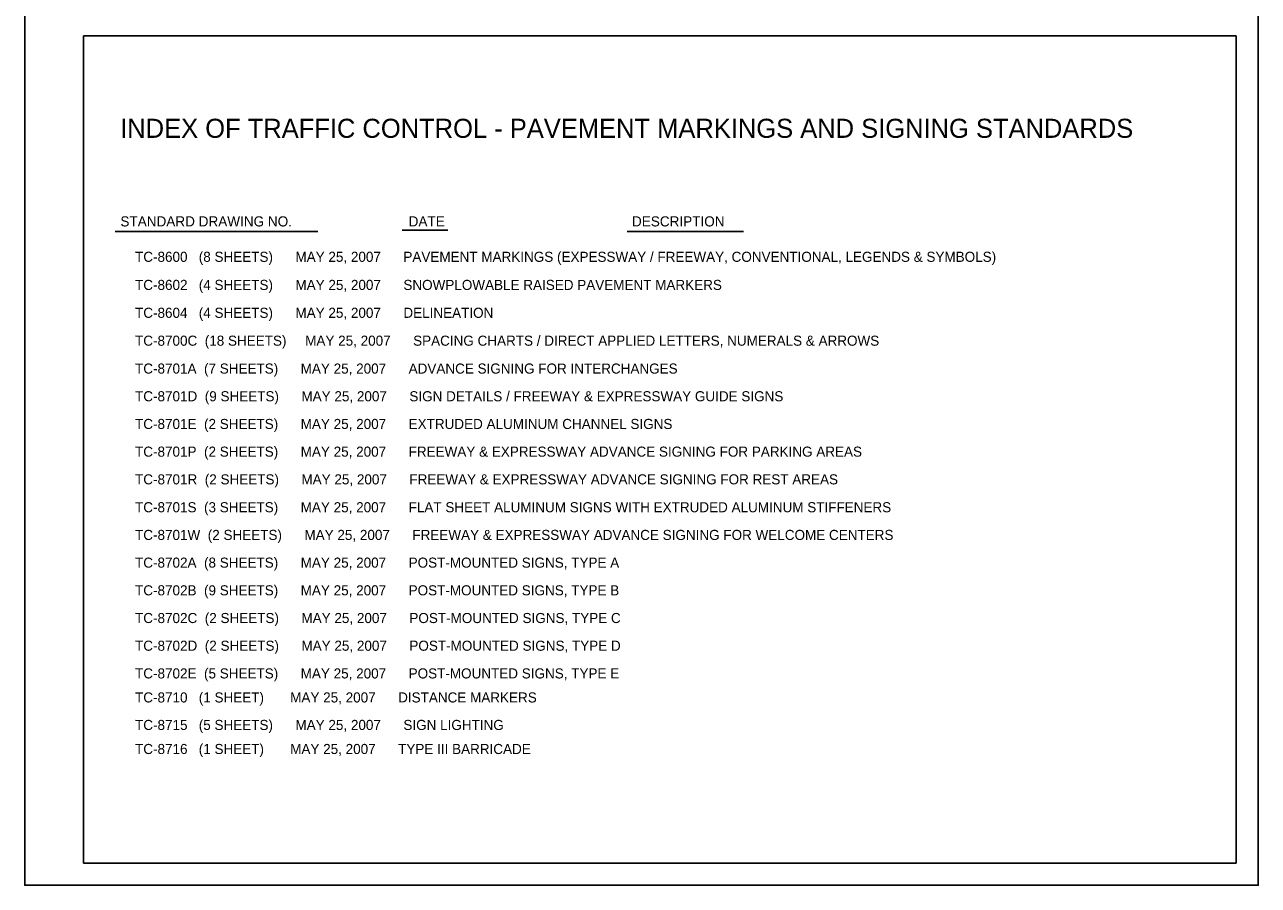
# Model space of a CAD drawing. Extents: x -1746 to -905, y 22 to 1210.
# Drawn here: x -1746 to -905, y 22 to 609 of the extents above; entities that cross this region are included whole.
import ezdxf

# ---------------------------------------------------------------- set-up
doc = ezdxf.new("R2010")
doc.units = 0
for name, color, linetype in [('Level 1', 7, 'Continuous'), ('Level 2', 7, 'Continuous'), ('PLT-BNDY', 7, 'Continuous')]:
    doc.layers.add(name, color=color, linetype=linetype)

msp = doc.modelspace()

# ---------------------------------------------------------------- linework, layer by layer
at = {"layer": 'Level 1'}
for p, q in [((-1706.14, 601.17), (-920.14, 601.17)), ((-1706.14, 37.17), (-1706.14, 601.17)), ((-920.14, 601.17), (-920.14, 37.17)), ((-920.14, 37.17), (-1706.14, 37.17))]:
    msp.add_line(p, q, dxfattribs=at)
at = {"layer": 'Level 2'}
for p, q in [((-1684.39, 467.67), (-1546.27, 467.67)), ((-1488.89, 468.67), (-1457.77, 468.67)), ((-1335.52, 467.67), (-1256.14, 467.67)), ((-1670.89, 453.92), (-1670.89, 453.92)), ((-1670.89, 415.77), (-1670.89, 415.77)), ((-1670.89, 396.77), (-1670.89, 396.77)), ((-1670.89, 377.89), (-1670.89, 377.89)), ((-1670.89, 321.14), (-1670.89, 321.14)), ((-1670.89, 302.27), (-1670.89, 302.27)), ((-1670.89, 245.64), (-1670.89, 245.64)), ((-1670.89, 226.64), (-1670.89, 226.64)), ((-1670.89, 207.77), (-1670.89, 207.77)), ((-1670.89, 188.89), (-1670.89, 188.89)), ((-1670.89, 170.02), (-1670.89, 170.02)), ((-1670.89, 134.89), (-1670.89, 134.89))]:
    msp.add_line(p, q, dxfattribs=at)
at = {"layer": 'PLT-BNDY'}
msp.add_lwpolyline([(-1746.14, 616.17), (-905.14, 616.17), (-905.14, 22.17), (-1746.14, 22.17)], close=True, dxfattribs=at)

# ---------------------------------------------------------------- texts
at = {"layer": 'Level 2'}
for s, height, p in [('INDEX OF TRAFFIC CONTROL - PAVEMENT MARKINGS AND SIGNING STANDARDS', 13, (-1681.03, 531.56)), ('STANDARD DRAWING NO.', 6.9067, (-1680.89, 471.17)), ('DATE', 6.907, (-1484.39, 471.17)), ('DESCRIPTION', 6.9067, (-1332.14, 471.17)), ('TC-8600   (8 SHEETS)      MAY 25, 2007      PAVEMENT MARKINGS (EXPESSWAY / FREEWAY, CONVENTIONAL, LEGENDS & SYMBOLS)', 6.87525, (-1670.89, 447.05)), ('TC-8602   (4 SHEETS)      MAY 25, 2007      SNOWPLOWABLE RAISED PAVEMENT MARKERS', 6.8753, (-1670.89, 427.89)), ('TC-8604   (4 SHEETS)      MAY 25, 2007      DELINEATION', 6.8753, (-1670.89, 408.89)), ('TC-8700C  (18 SHEETS)     MAY 25, 2007      SPACING CHARTS / DIRECT APPLIED LETTERS, NUMERALS & ARROWS', 6.87525, (-1670.89, 389.89)), ('TC-8701A  (7 SHEETS)      MAY 25, 2007      ADVANCE SIGNING FOR INTERCHANGES', 6.8753, (-1670.89, 370.89)), ('TC-8701D  (9 SHEETS)      MAY 25, 2007      SIGN DETAILS / FREEWAY & EXPRESSWAY GUIDE SIGNS', 6.8753, (-1670.89, 352.02)), ('TC-8701E  (2 SHEETS)      MAY 25, 2007      EXTRUDED ALUMINUM CHANNEL SIGNS', 6.8753, (-1670.89, 333.14)), ('TC-8701P  (2 SHEETS)      MAY 25, 2007      FREEWAY & EXPRESSWAY ADVANCE SIGNING FOR PARKING AREAS', 6.8753, (-1670.89, 314.27)), ('TC-8701R  (2 SHEETS)      MAY 25, 2007      FREEWAY & EXPRESSWAY ADVANCE SIGNING FOR REST AREAS', 6.8753, (-1670.89, 295.39)), ('TC-8701S  (3 SHEETS)      MAY 25, 2007      FLAT SHEET ALUMINUM SIGNS WITH EXTRUDED ALUMINUM STIFFENERS', 6.87525, (-1670.89, 276.39)), ('TC-8701W  (2 SHEETS)      MAY 25, 2007      FREEWAY & EXPRESSWAY ADVANCE SIGNING FOR WELCOME CENTERS', 6.8753, (-1670.89, 257.52)), ('TC-8702A  (8 SHEETS)      MAY 25, 2007      POST-MOUNTED SIGNS, TYPE A', 6.8753, (-1670.89, 238.64)), ('TC-8702B  (9 SHEETS)      MAY 25, 2007      POST-MOUNTED SIGNS, TYPE B', 6.8753, (-1670.89, 219.77)), ('TC-8702C  (2 SHEETS)      MAY 25, 2007      POST-MOUNTED SIGNS, TYPE C', 6.8753, (-1670.89, 200.89)), ('TC-8702D  (2 SHEETS)      MAY 25, 2007      POST-MOUNTED SIGNS, TYPE D', 6.8753, (-1670.89, 182.02)), ('TC-8702E  (5 SHEETS)      MAY 25, 2007      POST-MOUNTED SIGNS, TYPE E', 6.8753, (-1670.89, 163.14)), ('TC-8710   (1 SHEET)       MAY 25, 2007      DISTANCE MARKERS', 6.8753, (-1670.89, 146.77)), ('TC-8715   (5 SHEETS)      MAY 25, 2007      SIGN LIGHTING', 6.8753, (-1670.89, 128.02)), ('TC-8716   (1 SHEET)       MAY 25, 2007      TYPE III BARRICADE', 6.8753, (-1670.89, 111.64))]:
    msp.add_text(s, height=height, dxfattribs=at).set_placement(p)

doc.saveas('drawing.dxf')
